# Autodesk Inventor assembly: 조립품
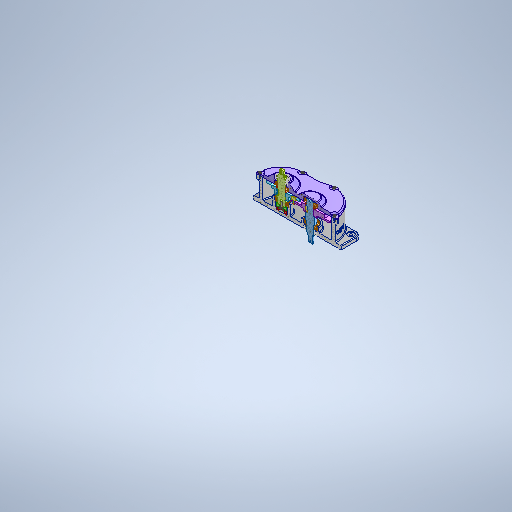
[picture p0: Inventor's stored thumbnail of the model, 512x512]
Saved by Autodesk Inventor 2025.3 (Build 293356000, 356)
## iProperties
Created: 2025-09
Part Number: 조립품
Document SubType Name: Assembly
Designer: PC-15
Author: PC-15
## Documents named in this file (19)
- C:\Users\PC-15\Desktop\750903V1010\조립품.iam
- C:\Users\PC-15\Desktop\750903V1010\본체.ipt
- C:\Users\PC-15\Desktop\750903V1010\6각 구멍붙이 볼트 M4x10\6각 구멍붙이 볼트 M4x10.ipt
- C:\Users\PC-15\Desktop\750903V1010\6각 구멍붙이 볼트 M6x12\6각 구멍붙이 볼트 M6x12.ipt
- C:\Users\PC-15\Desktop\750903V1010\구동 축\구동 축.ipt
- C:\Users\PC-15\Desktop\750903V1010\구동 휠\구동 휠.ipt
- C:\Users\PC-15\Desktop\750903V1010\깊은 홈 볼 베어링 6904\깊은 홈 볼 베어링 6904.ipt
- C:\Users\PC-15\Desktop\750903V1010\스러스트 볼 베어링 51102\스러스트 볼 베어링 51102.ipt
- C:\Users\PC-15\Desktop\750903V1010\스프링 와셔 M3\스프링 와셔 M3.ipt
- C:\Users\PC-15\Desktop\750903V1010\슬롯 축\슬롯 축.ipt
- C:\Users\PC-15\Desktop\750903V1010\슬롯\슬롯.ipt
- C:\Users\PC-15\Desktop\750903V1010\어댑터\어댑터.ipt
- C:\Users\PC-15\Desktop\750903V1010\오일 실 20 35 8\오일 실 20 35 8.ipt
- C:\Users\PC-15\Desktop\750903V1010\육각 너트 M3\육각 너트 M3.ipt
- C:\Users\PC-15\Desktop\750903V1010\칼라\칼라.ipt
- C:\Users\PC-15\Desktop\750903V1010\캠 플로워\캠 플로워.ipt
- C:\Users\PC-15\Desktop\750903V1010\커버\커버.ipt
- C:\Users\PC-15\Desktop\750903V1010\평 와셔 M3\평 와셔 M3.ipt
- C:\Users\PC-15\Desktop\750903V1010\평행 키 6x6x14\평행 키 6x6x14.ipt
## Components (9 placed, 4 different names)
1. 6각 구멍붙이 볼트 M4x10:1
2. 6각 구멍붙이 볼트 M6x12:1
3. 구동 축:1
4. 구동 휠:1
5. 6각 구멍붙이 볼트 M4x10:2
6. 6각 구멍붙이 볼트 M4x10:3
7. 6각 구멍붙이 볼트 M4x10:4
8. 6각 구멍붙이 볼트 M4x10:5
9. 6각 구멍붙이 볼트 M4x10:6
